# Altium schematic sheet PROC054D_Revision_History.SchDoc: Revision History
size 558 x 431 mm; Date: Not shown in title block; ApprovedBy: Not shown in title block; CheckedBy: Not shown in title block; Author: Not shown in title block; CompanyName: Not shown in title block; DrawnBy: a0271760; Engineer: Not shown in title block; Organization: Not shown in title block; Address1: Not shown in title block; Address2: Not shown in title block; Address3: Not shown in title block; Address4: Not shown in title block; DocumentNumber: 19; Revision: Use project pAWRameter SCH_Rev; SheetNumber: 19; SheetTotal: 19; PageSetup: Record=PageOptions¦CenterHorizontal=True¦CenterVertical=True¦PrintScale=1.00¦XCorrection=1.00¦YCorrection=1.00¦PrintKind=0¦BorderSize=5000000¦LeftOffset=0¦BottomOffset=0¦Orientation=2¦PaperLength=1000¦PaperWidth=1000¦Scale=100¦PaperSource=15¦PrintQuality=600¦MediaType=1¦DitherType=10¦PaperKind=Letter¦PrintScaleMode=1
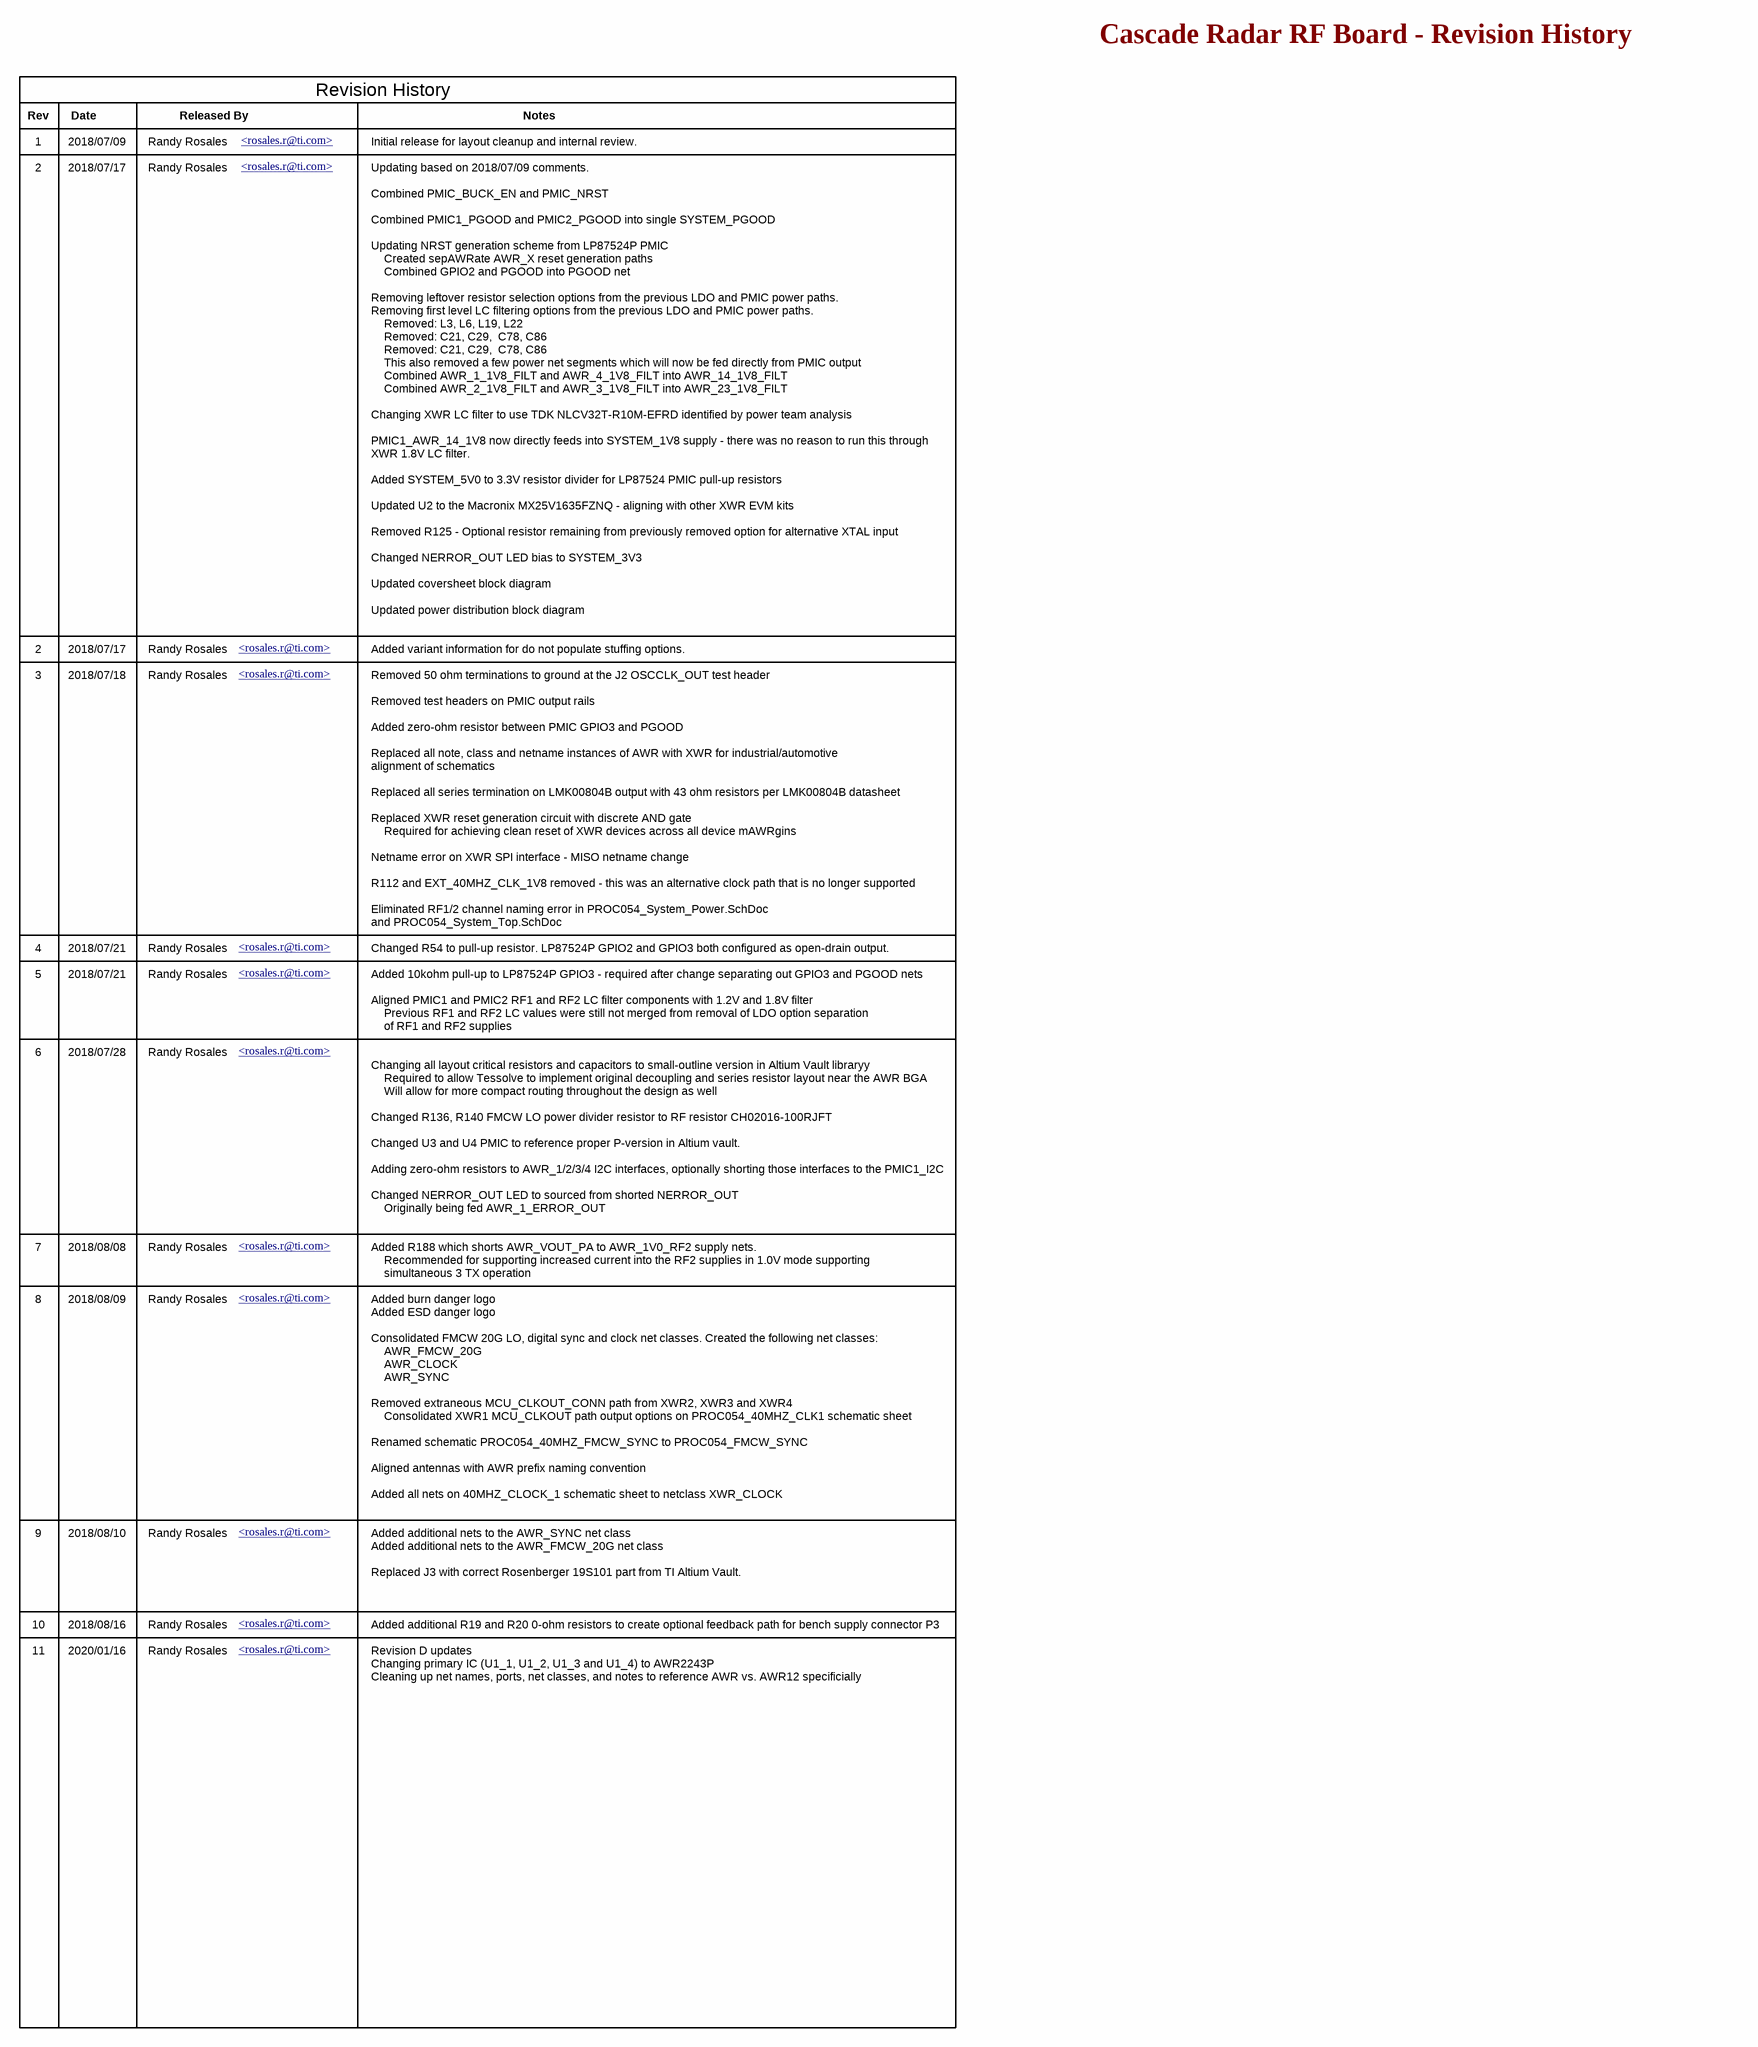
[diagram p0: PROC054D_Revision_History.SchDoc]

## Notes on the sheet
- Cascade Radar RF Board - Revision History
- Rev
- Date
- Released By
- Revision History
- Notes
- 1
- 2
- 2018/07/09
- 2018/07/17
- Randy Rosales
- <rosales.r@ti.com> <rosales.r@ti.com>
- Initial release for layout cleanup and internal review.
- Updating based on 2018/07/09 comments.
- Combined PMIC_BUCK_EN and PMIC_NRST
- Updating NRST generation scheme from LP87524P PMIC
- Combined PMIC1_PGOOD and PMIC2_PGOOD into single SYSTEM_PGOOD
- Created sepAWRate AWR_X reset generation paths
- Removing leftover resistor selection options from the previous LDO and PMIC power paths.
- Removing first level LC filtering options from the previous LDO and PMIC power paths.
- Removed: L3, L6, L19, L22
- Combined GPIO2 and PGOOD into PGOOD net
- Removed: C21, C29,  C78, C86
- This also removed a few power net segments which will now be fed directly from PMIC output
- Combined AWR_1_1V8_FILT and AWR_4_1V8_FILT into AWR_14_1V8_FILT
- Combined AWR_2_1V8_FILT and AWR_3_1V8_FILT into AWR_23_1V8_FILT
- Changing XWR LC filter to use TDK NLCV32T-R10M-EFRD identified by power team analysis
- PMIC1_AWR_14_1V8 now directly feeds into SYSTEM_1V8 supply - there was no reason to run this through
- XWR 1.8V LC filter.
- Updated U2 to the Macronix MX25V1635FZNQ - aligning with other XWR EVM kits
- Added SYSTEM_5V0 to 3.3V resistor divider for LP87524 PMIC pull-up resistors
- Removed R125 - Optional resistor remaining from previously removed option for alternative XTAL input
- Changed NERROR_OUT LED bias to SYSTEM_3V3
- Updated coversheet block diagram
- Updated power distribution block diagram
- Added variant information for do not populate stuffing options.
- 3
- 2018/07/18
- Removed 50 ohm terminations to ground at the J2 OSCCLK_OUT test header
- Removed test headers on PMIC output rails
- Added zero-ohm resistor between PMIC GPIO3 and PGOOD
- Replaced all note, class and netname instances of AWR with XWR for industrial/automotive
- alignment of schematics
- Replaced all series termination on LMK00804B output with 43 ohm resistors per LMK00804B datasheet
- Replaced XWR reset generation circuit with discrete AND gate
- Required for achieving clean reset of XWR devices across all device mAWRgins
- Netname error on XWR SPI interface - MISO netname change
- R112 and EXT_40MHZ_CLK_1V8 removed - this was an alternative clock path that is no longer supported
- Eliminated RF1/2 channel naming error in PROC054_System_Power.SchDoc
- 4
- 5
- 2018/07/21
- Changed R54 to pull-up resistor. LP87524P GPIO2 and GPIO3 both configured as open-drain output.
- and PROC054_System_Top.SchDoc
- Added 10kohm pull-up to LP87524P GPIO3 - required after change separating out GPIO3 and PGOOD nets
- Aligned PMIC1 and PMIC2 RF1 and RF2 LC filter components with 1.2V and 1.8V filter
- Previous RF1 and RF2 LC values were still not merged from removal of LDO option separation
- of RF1 and RF2 supplies
- 6
- 2018/07/28
- Changing all layout critical resistors and capacitors to small-outline version in Altium Vault libraryy
- Required to allow Tessolve to implement original decoupling and series resistor layout near the AWR BGA
- Will allow for more compact routing throughout the design as well
- Adding zero-ohm resistors to AWR_1/2/3/4 I2C interfaces, optionally shorting those interfaces to the PMIC1_I2C
- Changed R136, R140 FMCW LO power divider resistor to RF resistor CH02016-100RJFT
- Changed U3 and U4 PMIC to reference proper P-version in Altium vault.
- Changed NERROR_OUT LED to sourced from shorted NERROR_OUT
- Originally being fed AWR_1_ERROR_OUT
- 7
- 8
- 2018/08/08
- 2018/08/09
- Added R188 which shorts AWR_VOUT_PA to AWR_1V0_RF2 supply nets.
- Added burn danger logo
- Recommended for supporting increased current into the RF2 supplies in 1.0V mode supporting
- simultaneous 3 TX operation
- Added ESD danger logo
- Consolidated FMCW 20G LO, digital sync and clock net classes. Created the following net classes:
- AWR_FMCW_20G
- AWR_CLOCK
- Removed extraneous MCU_CLKOUT_CONN path from XWR2, XWR3 and XWR4
- Consolidated XWR1 MCU_CLKOUT path output options on PROC054_40MHZ_CLK1 schematic sheet
- AWR_SYNC
- Renamed schematic PROC054_40MHZ_FMCW_SYNC to PROC054_FMCW_SYNC
- Aligned antennas with AWR prefix naming convention
- Added all nets on 40MHZ_CLOCK_1 schematic sheet to netclass XWR_CLOCK
- 9
- 2018/08/10
- Added additional nets to the AWR_SYNC net class
- Added additional nets to the AWR_FMCW_20G net class
- 10
- 2018/08/16
- Replaced J3 with correct Rosenberger 19S101 part from TI Altium Vault.
- Added additional R19 and R20 0-ohm resistors to create optional feedback path for bench supply connector P3
- 11
- 2020/01/16
- Changing primary IC (U1_1, U1_2, U1_3 and U1_4) to AWR2243P
- Cleaning up net names, ports, net classes, and notes to reference AWR vs. AWR12 specificially
- Revision D updates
